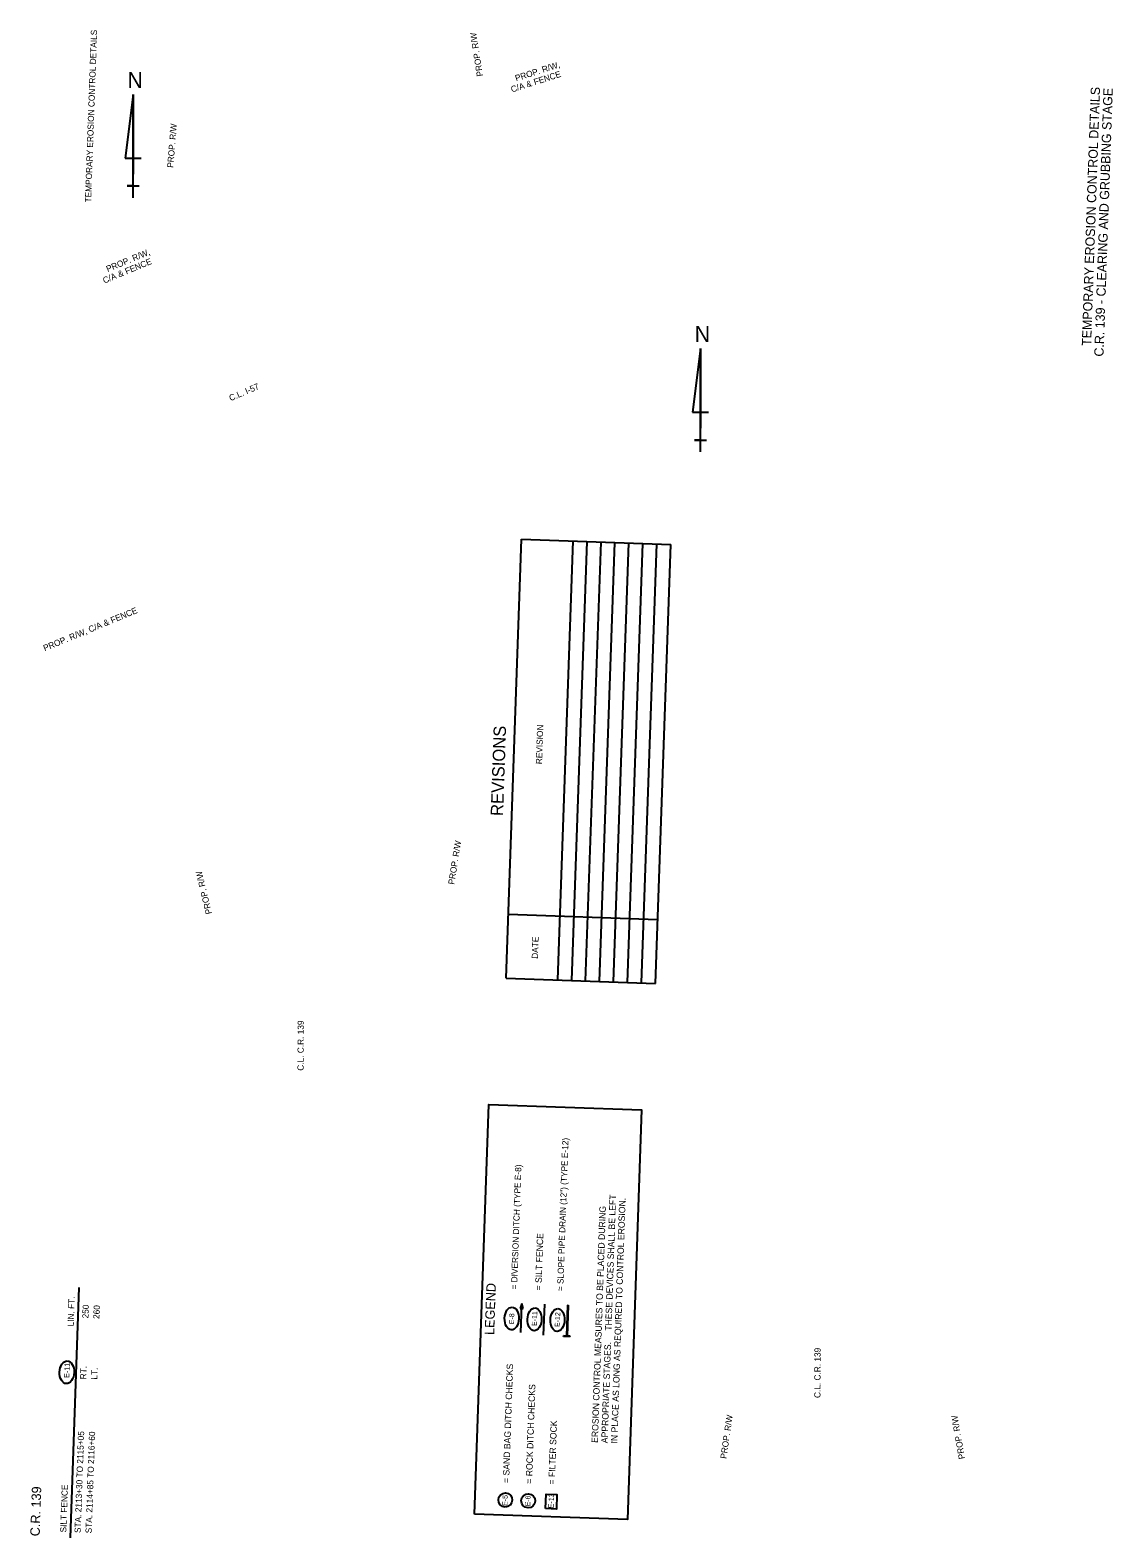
# Model space of a CAD drawing. Extents: x 1717345 to 1718393, y 765313 to 766772.
import ezdxf

# ---------------------------------------------------------------- set-up
doc = ezdxf.new("R2010")
doc.units = 0
for name, color, linetype in [('1', 7, 'Continuous'), ('44', 7, 'Continuous'), ('63', 7, 'Continuous'), ('Default', 7, 'Continuous'), ('G-ANNO-TEXT', 7, 'Continuous'), ('Level 1', 7, 'Continuous'), ('Level 44', 7, 'Continuous'), ('R_Draft', 7, 'Continuous')]:
    doc.layers.add(name, color=color, linetype=linetype)

msp = doc.modelspace()

# ---------------------------------------------------------------- linework, layer by layer
at = {"layer": '1'}
for points in [[(1717775.3, 765335.8), (1717789.1, 765732.2), (1717936.9, 765727), (1717923.1, 765330.6)], [(1717843.9, 765341.2), (1717844.4, 765355.2), (1717854.9, 765354.8), (1717854.4, 765340.8)]]:
    msp.add_lwpolyline(points, close=True, dxfattribs=at)
msp.add_ellipse((1717380.8, 765473.1), major_axis=(0.4, 11), ratio=0.638788, dxfattribs=at)
at = {"layer": '44'}
msp.add_line((1717384.3, 765312.9), (1717392.8, 765555.2), dxfattribs=at)
at = {"layer": '63'}
for p, q in [((1717445.1, 766709.4), (1717437.4, 766647.9)), ((1717445.1, 766609.4), (1717445.1, 766709.4)), ((1717445.1, 766709.4), (1717445.1, 766632.5)), ((1717437.4, 766647.9), (1717452.8, 766647.9)), ((1717445.1, 766609.4), (1717445.1, 766632.5)), ((1717445.1, 766621), (1717439.3, 766621)), ((1717439.3, 766621), (1717450.9, 766621)), ((1717445.1, 766609.4), (1717445.1, 766621)), ((1717993.8, 766463.7), (1717986.2, 766402.2)), ((1717993.8, 766363.7), (1717993.8, 766463.7)), ((1717993.8, 766463.7), (1717993.8, 766386.8)), ((1717986.2, 766402.2), (1718001.5, 766402.2)), ((1717993.8, 766363.7), (1717993.8, 766386.8)), ((1717993.8, 766375.2), (1717988.1, 766375.2)), ((1717988.1, 766375.2), (1717999.6, 766375.2)), ((1717993.8, 766363.7), (1717993.8, 766375.2))]:
    msp.add_line(p, q, dxfattribs=at)
at = {"layer": 'Default'}
for p, q in [((1717805.8, 765854.5), (1717820.6, 766279.2)), ((1717820.6, 766279.2), (1717965, 766274.2)), ((1717855.8, 765852.7), (1717870.6, 766277.5)), ((1717869.3, 765852.3), (1717884.1, 766277)), ((1717882.7, 765851.8), (1717897.6, 766276.5)), ((1717896.2, 765851.3), (1717911.1, 766276.1)), ((1717896.2, 765851.3), (1717911.1, 766276.1)), ((1717909.7, 765850.9), (1717924.6, 766275.6)), ((1717923.2, 765850.4), (1717938.1, 766275.1)), ((1717936.7, 765849.9), (1717951.5, 766274.7)), ((1717950.2, 765849.4), (1717965, 766274.2)), ((1717808, 765916.3), (1717952.4, 765911.2)), ((1717805.8, 765854.5), (1717950.2, 765849.4))]:
    msp.add_line(p, q, dxfattribs=at)
at = {"layer": 'Level 1'}
for p, q in [((1717821, 765539.7), (1717819.4, 765534.9)), ((1717819.4, 765534.9), (1717822.3, 765534.8)), ((1717820.7, 765538.4), (1717819.7, 765534.9)), ((1717820.8, 765538.4), (1717820.1, 765534.9)), ((1717820.9, 765538.4), (1717820.5, 765534.9)), ((1717822.3, 765534.8), (1717821, 765539.7)), ((1717821.5, 765534.9), (1717821.1, 765538.4)), ((1717821.2, 765534.9), (1717821.1, 765538.4)), ((1717821.9, 765534.8), (1717821.2, 765538.4))]:
    msp.add_line(p, q, dxfattribs=at)
msp.add_lwpolyline([(1717820, 765511.5), (1717820.9, 765538)], dxfattribs=at)
for centre, major_axis, ratio in [((1717811.2, 765525.1), (0.4, 11), 0.622952), ((1717833.3, 765524.3), (0.4, 11), 0.622952), ((1717855.5, 765523.7), (0.4, 11), 0.622952), ((1717805, 765349.5), (-0.23, -6.88), 0.97521), ((1717827.2, 765348.7), (-0.23, -6.88), 0.97521)]:
    msp.add_ellipse(centre, major_axis=major_axis, ratio=ratio, dxfattribs=at)
at = {"layer": 'Level 44'}
for p, q in [((1717865.3, 765538.1), (1717864.3, 765508.2)), ((1717865.8, 765538.1), (1717864.8, 765508.2)), ((1717865.3, 765538.1), (1717865.8, 765538.1)), ((1717864.3, 765508.2), (1717861.2, 765508.3)), ((1717861.2, 765507.8), (1717861.2, 765508.3)), ((1717867.9, 765507.6), (1717861.2, 765507.8)), ((1717867.9, 765508.1), (1717864.8, 765508.2)), ((1717867.9, 765507.6), (1717867.9, 765508.1))]:
    msp.add_line(p, q, dxfattribs=at)
msp.add_lwpolyline([(1717842.1, 765509), (1717843.1, 765539.1)], dxfattribs=at)

# ---------------------------------------------------------------- texts
at = {"layer": '1'}
for s, rotation, p in [('E-11', 88, (1717383.1, 765467.6)), ('E-13', 87.6177, (1717851.6, 765341.3))]:
    msp.add_text(s, height=5, rotation=rotation, dxfattribs=at).set_placement(p)
at = {"layer": '44'}
for s, p in [('LIN. FT.', (1717387.5, 765517.4)), ('250', (1717401.7, 765525.1)), ('260', (1717412.3, 765524.6)), ('RT.', (1717399.6, 765466.2)), ('LT.', (1717410.2, 765466)), ('STA. 2113+30 TO 2115+05', (1717394.2, 765317.5)), ('STA. 2114+85 TO 2116+60 ', (1717404.8, 765317.2)), ('SILT FENCE      ', (1717380.3, 765318))]:
    msp.add_text(s, height=6, rotation=88, dxfattribs=at).set_placement(p)
at = {"layer": '63'}
for p in [(1717439.5, 766715.8), (1717988.2, 766470.1)]:
    msp.add_text('N', height=15.4, rotation=360, dxfattribs=at).set_placement(p)
at = {"layer": 'Default'}
for s, height, p in [('REVISION', 6, (1717840.5, 766061.4)), ('REVISIONS', 12, (1717802.8, 766011.2)), ('DATE', 6, (1717836.5, 765873.1))]:
    msp.add_text(s, height=height, rotation=88, dxfattribs=at).set_placement(p)
at = {"layer": 'G-ANNO-TEXT'}
for s, height, p in [('TEMPORARY EROSION CONTROL DETAILS', 6, (1717404.3, 766605)), ('TEMPORARY EROSION CONTROL DETAILS', 9, (1718371.7, 766466.1)), ('C.R. 139 - CLEARING AND GRUBBING STAGE', 9, (1718383.7, 766455.8))]:
    msp.add_text(s, height=height, rotation=88, dxfattribs=at).set_placement(p)
at = {"layer": 'Level 1'}
for s, height, rotation, p in [('= SLOPE PIPE DRAIN (12") (TYPE E-12)', 6, 88, (1717861, 765551.5)), ('= DIVERSION DITCH (TYPE E-8)', 6, 88, (1717816.4, 765553.1)), ('EROSION CONTROL MEASURES TO BE PLACED DURING', 6.25, 88.058, (1717894.6, 765404.7)), ('THESE DEVICES SHALL BE LEFT', 6.25, 88.058, (1717907.7, 765513.2)), ('IN PLACE AS LONG AS REQUIRED TO CONTROL EROSION.', 6.25, 88.058, (1717913.4, 765404.1)), ('= SILT FENCE', 6.25, 88.058, (1717840, 765552.2)), ('E-8', 4.88, 88, (1717813.4, 765519.6)), ('E-11 ', 4.88, 88.058, (1717835.5, 765517.9)), ('E-12', 4.88, 88, (1717857.7, 765516.9)), ('APPROPRIATE STAGES. ', 6.25, 88.058, (1717904, 765404.4)), ('= SAND BAG DITCH CHECKS', 6.25, 88.058, (1717808.7, 765365.9)), ('= ROCK DITCH CHECKS', 6.25, 88.058, (1717830.9, 765365.2)), ('= FILTER SOCK', 6.25, 88, (1717852.9, 765364.4)), ('E-5 ', 4.88, 88.058, (1717807, 765343.8)), ('E-6 ', 4.88, 88.058, (1717829.1, 765343.3))]:
    msp.add_text(s, height=height, rotation=rotation, dxfattribs=at).set_placement(p)
at = {"layer": 'Level 44'}
for s, rotation, p in [('LEGEND', 88.058, (1717794.2, 765509.1)), ('C.R. 139', 88, (1717354.5, 765314.3))]:
    msp.add_text(s, height=9.14, rotation=rotation, dxfattribs=at).set_placement(p)
at = {"layer": 'R_Draft'}
for s, rotation, p in [('PROP. R/W', 99.0183, (1717783.5, 766727.5)), ('PROP. R/W, ', 17.8147, (1717815.6, 766722.2)), ('C/A & FENCE', 17.8147, (1717811.5, 766711.4)), ('PROP. R/W', 85.3201, (1717483.8, 766638.4)), ('C/A & FENCE', 22.5, (1717417.1, 766526.5)), ('PROP. R/W, ', 22.5, (1717420.4, 766537.6)), ('C.L. I-57', 23.2911, (1717539.3, 766412.7)), ('PROP. R/W, C/A & FENCE', 22.5, (1717359.5, 766170.7)), ('PROP. R/W', 80.8828, (1717755.6, 765944.7)), ('PROP. R/W', 103.574, (1717521.3, 765917.1)), ('C.L. C.R. 139', 89.7759, (1717609.9, 765764.9)), ('C.L. C.R. 139', 89.7759, (1718109.9, 765448.2)), ('PROP. R/W', 81.7087, (1718018.9, 765389.1)), ('PROP. R/W', 100.0665, (1718249.8, 765389.6))]:
    msp.add_text(s, height=6, rotation=rotation, dxfattribs=at).set_placement(p)

doc.saveas('drawing.dxf')
